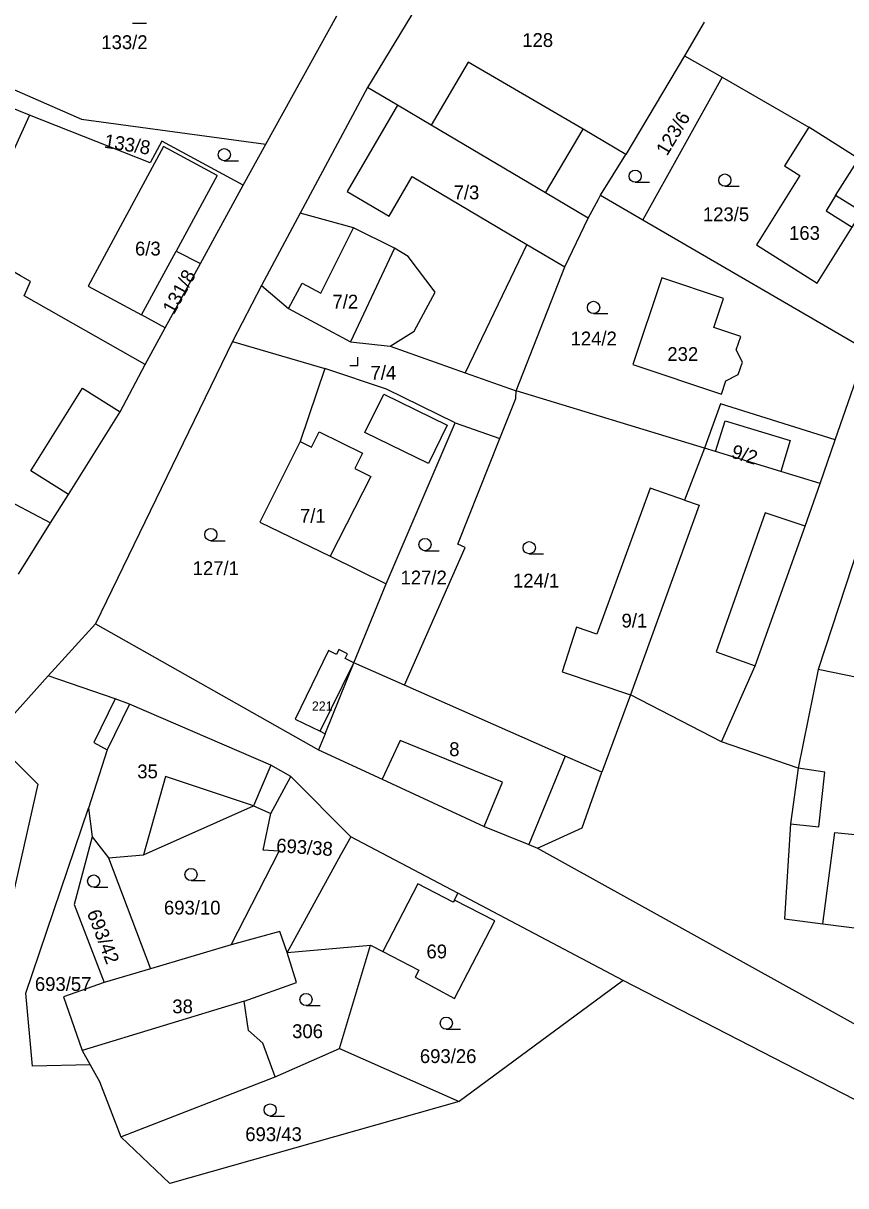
# Model space of a CAD drawing. Extents: x -7483133 to -743169, y -11317770 to -1127091.
# Drawn here: x -746438.1 to -746337, y -1132088.9 to -1131945.9 of the extents above; entities that cross this region are included whole.
import ezdxf

# ---------------------------------------------------------------- set-up
doc = ezdxf.new("R2010")
doc.units = 0
for name, color, linetype in [('Hranice parcel', 7, 'Continuous'), ('Parcelní čísla', 7, 'Continuous'), ('Vnitřní kresba', 7, 'Continuous'), ('Značky kultur', 7, 'Continuous')]:
    doc.layers.add(name, color=color, linetype=linetype)

msp = doc.modelspace()

# ---------------------------------------------------------------- linework, layer by layer
at = {"layer": 'Hranice parcel'}
for p, q in [((-746381.8, -1131930.69), (-746395.75, -1131953.81)), ((-746408.25, -1131960.77), (-746399.53, -1131945)), ((-746354.37, -1131945.76), (-746356.8, -1131949.89)), ((-746437.32, -1131957.2), (-746455.89, -1131949.78)), ((-746356.8, -1131949.89), (-746364, -1131962.05)), ((-746356.8, -1131949.89), (-746352.16, -1131952.55)), ((-746395.75, -1131953.81), (-746404.04, -1131969.28)), ((-746352.16, -1131952.55), (-746361.91, -1131970.09)), ((-746352.16, -1131952.55), (-746341.49, -1131958.67)), ((-746437.32, -1131957.2), (-746444.69, -1131973.38)), ((-746335.36, -1131962.56), (-746341.49, -1131958.67)), ((-746411.04, -1131965.81), (-746408.25, -1131960.77)), ((-746367.12, -1131967.06), (-746364, -1131962.05)), ((-746416.31, -1131975.44), (-746411.04, -1131965.81)), ((-746368.62, -1131969.86), (-746367.37, -1131967.53)), ((-746367.37, -1131967.53), (-746367.12, -1131967.06)), ((-746367.12, -1131967.06), (-746361.91, -1131970.09)), ((-746404.04, -1131969.28), (-746408.81, -1131978.18)), ((-746361.91, -1131970.09), (-746334.41, -1131986.06)), ((-746420.64, -1131983.36), (-746416.31, -1131975.44)), ((-746408.81, -1131978.18), (-746412.35, -1131985.06)), ((-746408.81, -1131978.18), (-746405.47, -1131981.01)), ((-746420.64, -1131983.36), (-746423.54, -1131981.79)), ((-746423.09, -1131987.89), (-746420.64, -1131983.36)), ((-746412.35, -1131985.06), (-746429.19, -1132019.77)), ((-746412.35, -1131985.06), (-746400.99, -1131988.36)), ((-746338.25, -1131997.16), (-746334.41, -1131986.06)), ((-746400.99, -1131988.36), (-746404.05, -1131997.34)), ((-746354.34, -1131998.17), (-746377.47, -1131991.14)), ((-746393.46, -1132014.85), (-746384.98, -1131995.05)), ((-746384.98, -1131995.05), (-746379.47, -1131997)), ((-746340.11, -1132002.51), (-746338.25, -1131997.16)), ((-746445.14, -1132001.9), (-746434.75, -1132007.36)), ((-746438.69, -1132013.68), (-746434.75, -1132007.36)), ((-746335.32, -1132010.03), (-746340.35, -1132025.42)), ((-746397.45, -1132024.58), (-746393.46, -1132014.85)), ((-746435.02, -1132026.19), (-746429.19, -1132019.77)), ((-746429.19, -1132019.77), (-746401.77, -1132035.28)), ((-746400.98, -1132033.31), (-746397.45, -1132024.58)), ((-746391.22, -1132027.33), (-746397.45, -1132024.58)), ((-746340.35, -1132025.42), (-746342.81, -1132037.56)), ((-746441.94, -1132033.89), (-746435.02, -1132026.19)), ((-746426.8, -1132029.03), (-746435.02, -1132026.19)), ((-746363.4, -1132028.51), (-746366.94, -1132038.04)), ((-746352.22, -1132034.3), (-746363.4, -1132028.51)), ((-746400.98, -1132033.31), (-746401.77, -1132035.28)), ((-746401.6, -1132033.01), (-746400.98, -1132033.31)), ((-746401.77, -1132035.28), (-746393.96, -1132038.89)), ((-746342.81, -1132037.56), (-746352.22, -1132034.3)), ((-746407.66, -1132043.13), (-746405.2, -1132038.56)), ((-746397.81, -1132045.97), (-746405.2, -1132038.56)), ((-746393.96, -1132038.89), (-746381.4, -1132044.7)), ((-746430.06, -1132042.48), (-746429.6, -1132046.01)), ((-746429.6, -1132046.01), (-746427.59, -1132048.57)), ((-746384.64, -1132052.93), (-746397.81, -1132045.97)), ((-746374.84, -1132047.38), (-746324.12, -1132075.54)), ((-746427.59, -1132048.57), (-746422.45, -1132062.24)), ((-746385.07, -1132053.77), (-746384.64, -1132052.93)), ((-746364.32, -1132063.67), (-746384.64, -1132052.93)), ((-746412.54, -1132059.26), (-746422.45, -1132062.24)), ((-746405.65, -1132060.22), (-746395.38, -1132059.32)), ((-746399.22, -1132072.05), (-746395.38, -1132059.32)), ((-746422.45, -1132062.24), (-746428.14, -1132063.91)), ((-746364.32, -1132063.67), (-746384.5, -1132078.54)), ((-746407.1, -1132075.5), (-746399.22, -1132072.05)), ((-746399.22, -1132072.05), (-746384.5, -1132078.54)), ((-746426.1, -1132082.89), (-746407.1, -1132075.5))]:
    msp.add_line(p, q, dxfattribs=at)
for points in [[(-746453.89, -1131947.67), (-746430.93, -1131957.68), (-746408.25, -1131960.77)], [(-746383.37, -1131950.7), (-746387.94, -1131958.43), (-746392.06, -1131955.99), (-746395.75, -1131953.81)], [(-746364, -1131962.05), (-746369.24, -1131958.95), (-746383.37, -1131950.7)], [(-746411.04, -1131965.81), (-746421.04, -1131960.39), (-746422.49, -1131963.07), (-746437.32, -1131957.2)], [(-746341.49, -1131958.67), (-746344.48, -1131963.46), (-746342.61, -1131964.63), (-746347.93, -1131973.15), (-746340.47, -1131977.86), (-746336.17, -1131971), (-746334.98, -1131969.11), (-746338.2, -1131967.09), (-746335.36, -1131962.56)], [(-746392.96, -1131985.62), (-746390.02, -1131983.77), (-746387.42, -1131978.99), (-746390.76, -1131974.61), (-746392.46, -1131973.55), (-746397.49, -1131971.05), (-746404.04, -1131969.28)], [(-746377.47, -1131991.14), (-746371.48, -1131975.87), (-746368.62, -1131969.86)], [(-746423.09, -1131987.89), (-746437.98, -1131979.44), (-746437.18, -1131977.66), (-746438.41, -1131976.96), (-746444.69, -1131973.38)], [(-746423.54, -1131981.79), (-746419.29, -1131973.93), (-746416.31, -1131975.44)], [(-746351.98, -1131979.75), (-746359.57, -1131977.21), (-746363.14, -1131987.9), (-746352.22, -1131991.54), (-746351.68, -1131989.88), (-746350.17, -1131989.11), (-746349.66, -1131987.58), (-746350.41, -1131986.06), (-746349.86, -1131984.42), (-746353.17, -1131983.31), (-746351.98, -1131979.75)], [(-746405.47, -1131981.01), (-746397.86, -1131985.09), (-746392.96, -1131985.62)], [(-746392.96, -1131985.62), (-746383.74, -1131988.91), (-746377.47, -1131991.14)], [(-746434.75, -1132007.36), (-746432.53, -1132003.87), (-746426.16, -1131993.7), (-746423.09, -1131987.89)], [(-746384.98, -1131995.05), (-746393.44, -1131990.91), (-746400.99, -1131988.36)], [(-746379.47, -1131997), (-746377.51, -1131992.07), (-746377.47, -1131991.14)], [(-746338.25, -1131997.16), (-746352.35, -1131992.71), (-746354.34, -1131998.17)], [(-746404.05, -1131997.34), (-746409, -1132007.27), (-746400.37, -1132011.48), (-746393.46, -1132014.85)], [(-746391.22, -1132027.33), (-746383.75, -1132010.4), (-746384.66, -1132010), (-746379.47, -1131997)], [(-746354.34, -1131998.17), (-746356.76, -1132004.57), (-746361.01, -1132003.1), (-746367.57, -1132021.06), (-746370.07, -1132020.2), (-746371.84, -1132025.7), (-746363.4, -1132028.51)], [(-746340.11, -1132002.51), (-746344.93, -1132001.03), (-746352.95, -1131998.59), (-746354.34, -1131998.17)], [(-746352.22, -1132034.3), (-746348.1, -1132024.97), (-746341.94, -1132007.79), (-746340.11, -1132002.51)], [(-746397.45, -1132024.58), (-746398.5, -1132024.07), (-746398.22, -1132023.48), (-746399.27, -1132022.95), (-746399.56, -1132023.55), (-746400.54, -1132023.07), (-746404.66, -1132031.52), (-746401.6, -1132033.01)], [(-746333.61, -1132057.47), (-746332.67, -1132049.65), (-746332.24, -1132046.07), (-746330.4, -1132030.76), (-746330, -1132027.47), (-746335.35, -1132026.41), (-746340.35, -1132025.42)], [(-746366.94, -1132038.04), (-746371.46, -1132036.05), (-746391.22, -1132027.33)], [(-746426.8, -1132029.03), (-746429.42, -1132034.4), (-746427.78, -1132035.27), (-746430.06, -1132042.48)], [(-746405.2, -1132038.56), (-746407.63, -1132037.16), (-746425.03, -1132029.66), (-746426.8, -1132029.03)], [(-746441.94, -1132033.89), (-746436.31, -1132039.52), (-746440.38, -1132057.72)], [(-746374.84, -1132047.38), (-746369.36, -1132044.89), (-746366.94, -1132038.04)], [(-746342.81, -1132037.56), (-746343.73, -1132044.39), (-746344.5, -1132056.09), (-746339.75, -1132056.69), (-746333.61, -1132057.47)], [(-746429.86, -1132074.04), (-746436.96, -1132074.19), (-746437.77, -1132065.23), (-746430.06, -1132042.48)], [(-746427.59, -1132048.57), (-746423.29, -1132048.22), (-746409.79, -1132042.16), (-746407.66, -1132043.13)], [(-746412.54, -1132059.26), (-746406.61, -1132047.75), (-746408.61, -1132047.62), (-746407.66, -1132043.13)], [(-746381.4, -1132044.7), (-746375.91, -1132046.94), (-746374.84, -1132047.38)], [(-746429.6, -1132046.01), (-746431.83, -1132054.3), (-746428.14, -1132063.91)], [(-746397.81, -1132045.97), (-746399.07, -1132048.25), (-746405.65, -1132060.22)], [(-746395.38, -1132059.32), (-746393.88, -1132060.1), (-746389.45, -1132062.38), (-746389.91, -1132063.27), (-746385.05, -1132065.88), (-746380.12, -1132056.33), (-746385.07, -1132053.77)], [(-746405.65, -1132060.22), (-746406.55, -1132057.63), (-746412.54, -1132059.26)], [(-746407.1, -1132075.5), (-746408.64, -1132071.36), (-746410.41, -1132069.82), (-746410.94, -1132066.21), (-746404.49, -1132063.91), (-746405.65, -1132060.22)], [(-746428.14, -1132063.91), (-746433.13, -1132065.67), (-746430.83, -1132072.28), (-746429.86, -1132074.04)], [(-746281.98, -1132106.18), (-746317.29, -1132087.85), (-746364.32, -1132063.67)], [(-746429.86, -1132074.04), (-746428.72, -1132076.1), (-746426.1, -1132082.89)], [(-746384.5, -1132078.54), (-746420.08, -1132088.64), (-746426.1, -1132082.89)]]:
    msp.add_lwpolyline(points, dxfattribs=at)
at = {"layer": 'Vnitřní kresba'}
for p, q in [((-746392.06, -1131955.99), (-746398.27, -1131966.61)), ((-746373.86, -1131966.76), (-746387.94, -1131958.43)), ((-746373.86, -1131966.76), (-746369.24, -1131958.95)), ((-746420.84, -1131961.07), (-746430.12, -1131978.23)), ((-746414.26, -1131964.63), (-746420.84, -1131961.07)), ((-746414.26, -1131964.63), (-746419.29, -1131973.93)), ((-746393.11, -1131969.63), (-746390.26, -1131964.74)), ((-746390.26, -1131964.74), (-746376.15, -1131973.1)), ((-746398.27, -1131966.61), (-746393.11, -1131969.63)), ((-746368.62, -1131969.86), (-746373.86, -1131966.76)), ((-746338.2, -1131967.09), (-746339.38, -1131968.98)), ((-746339.38, -1131968.98), (-746336.17, -1131971)), ((-746401.49, -1131979.09), (-746397.49, -1131971.05)), ((-746392.46, -1131973.55), (-746397.86, -1131985.09)), ((-746376.15, -1131973.1), (-746383.74, -1131988.91)), ((-746376.15, -1131973.1), (-746371.48, -1131975.87)), ((-746430.12, -1131978.23), (-746423.54, -1131981.79)), ((-746405.47, -1131981.01), (-746403.78, -1131977.86)), ((-746403.78, -1131977.86), (-746401.49, -1131979.09)), ((-746437.16, -1132000.97), (-746430.81, -1131990.79)), ((-746430.81, -1131990.79), (-746426.16, -1131993.7)), ((-746396.07, -1131996.26), (-746393.75, -1131991.54)), ((-746393.75, -1131991.54), (-746385.96, -1131995.34)), ((-746385.96, -1131995.34), (-746388.24, -1132000.05)), ((-746352.95, -1131998.59), (-746351.8, -1131994.81)), ((-746351.8, -1131994.81), (-746343.78, -1131997.25)), ((-746402.65, -1131998.04), (-746401.71, -1131996.16)), ((-746401.71, -1131996.16), (-746396.39, -1131998.81)), ((-746388.24, -1132000.05), (-746396.07, -1131996.26)), ((-746404.05, -1131997.34), (-746402.65, -1131998.04)), ((-746343.78, -1131997.25), (-746344.93, -1132001.03)), ((-746396.39, -1131998.81), (-746397.32, -1132000.69)), ((-746432.53, -1132003.87), (-746437.16, -1132000.97)), ((-746397.32, -1132000.69), (-746395.34, -1132001.68)), ((-746395.34, -1132001.68), (-746400.37, -1132011.48)), ((-746354.99, -1132005.18), (-746363.4, -1132028.51)), ((-746356.76, -1132004.57), (-746354.99, -1132005.18)), ((-746346.85, -1132006.12), (-746352.9, -1132023.25)), ((-746341.94, -1132007.79), (-746346.85, -1132006.12)), ((-746352.9, -1132023.25), (-746348.1, -1132024.97)), ((-746401.6, -1132033.01), (-746397.45, -1132024.58)), ((-746425.03, -1132029.66), (-746427.78, -1132035.27)), ((-746391.76, -1132034.12), (-746393.96, -1132038.89)), ((-746379.18, -1132039.26), (-746391.76, -1132034.12)), ((-746371.46, -1132036.05), (-746375.91, -1132046.94)), ((-746407.63, -1132037.16), (-746409.79, -1132042.16)), ((-746339.51, -1132038.02), (-746342.81, -1132037.56)), ((-746340.28, -1132044.78), (-746339.51, -1132038.02)), ((-746420.61, -1132038.55), (-746423.29, -1132048.22)), ((-746409.79, -1132042.16), (-746420.61, -1132038.55)), ((-746381.4, -1132044.7), (-746379.18, -1132039.26)), ((-746343.73, -1132044.39), (-746340.28, -1132044.78)), ((-746339.75, -1132056.69), (-746338.28, -1132045.47)), ((-746338.28, -1132045.47), (-746332.24, -1132046.07)), ((-746389.59, -1132051.78), (-746393.88, -1132060.1)), ((-746385.21, -1132054.04), (-746389.59, -1132051.78)), ((-746385.07, -1132053.77), (-746385.21, -1132054.04)), ((-746410.94, -1132066.21), (-746430.83, -1132072.28))]:
    msp.add_line(p, q, dxfattribs=at)
at = {"layer": 'Značky kultur'}
for p, q in [((-746424.67, -1131945.9), (-746422.92, -1131945.9)), ((-746413.37, -1131962.82), (-746411.62, -1131962.82)), ((-746362.84, -1131965.46), (-746361.09, -1131965.46)), ((-746351.82, -1131965.94), (-746350.07, -1131965.94)), ((-746367.96, -1131981.61), (-746366.21, -1131981.61)), ((-746397.94, -1131988), (-746396.94, -1131988)), ((-746396.94, -1131988), (-746396.94, -1131987)), ((-746415.03, -1132009.56), (-746413.28, -1132009.56)), ((-746388.69, -1132010.79), (-746386.94, -1132010.79)), ((-746375.87, -1132011.17), (-746374.12, -1132011.17)), ((-746429.43, -1132052.18), (-746427.68, -1132052.18)), ((-746417.46, -1132051.37), (-746415.71, -1132051.37)), ((-746403.32, -1132066.75), (-746401.57, -1132066.75)), ((-746386.07, -1132069.67), (-746384.32, -1132069.67)), ((-746407.73, -1132080.34), (-746405.98, -1132080.34))]:
    msp.add_line(p, q, dxfattribs=at)
for centre in [(-746413.37, -1131962.07), (-746362.84, -1131964.71), (-746351.82, -1131965.19), (-746367.96, -1131980.86), (-746415.03, -1132008.81), (-746388.69, -1132010.04), (-746375.87, -1132010.42), (-746429.43, -1132051.43), (-746417.46, -1132050.62), (-746403.32, -1132066), (-746386.07, -1132068.92), (-746407.73, -1132079.59)]:
    msp.add_circle(centre, 0.75, dxfattribs=at)

# ---------------------------------------------------------------- texts
at = {"layer": 'Parcelní čísla'}
for s, height, p in [('133/2', 1.7, (-746428.49, -1131949.08)), ('128', 1.7, (-746376.73, -1131948.82)), ('7/3', 1.7, (-746385.17, -1131967.56)), ('123/5', 1.7, (-746354.52, -1131970.25)), ('163', 1.7, (-746343.92, -1131972.55)), ('6/3', 1.7, (-746424.35, -1131974.47)), ('7/2', 1.7, (-746400.07, -1131981)), ('124/2', 1.7, (-746370.79, -1131985.53)), ('232', 1.7, (-746358.89, -1131987.45)), ('7/4', 1.7, (-746395.39, -1131989.75)), ('7/1', 1.7, (-746404.06, -1132007.34)), ('127/1', 1.7, (-746417.26, -1132013.79)), ('127/2', 1.7, (-746391.7, -1132014.94)), ('124/1', 1.7, (-746377.87, -1132015.32)), ('9/1', 1.7, (-746364.52, -1132020.24)), ('221', 1.14, (-746402.6, -1132030.48)), ('8', 1.7, (-746385.71, -1132036.06)), ('35', 1.7, (-746424.07, -1132038.79)), ('693/10', 1.7, (-746420.79, -1132055.55)), ('69', 1.7, (-746388.51, -1132060.94)), ('693/57', 1.7, (-746436.66, -1132064.95)), ('38', 1.7, (-746419.76, -1132067.7)), ('306', 1.7, (-746405.03, -1132070.75)), ('693/26', 1.7, (-746389.32, -1132073.82)), ('693/43', 1.7, (-746410.79, -1132083.42))]:
    msp.add_text(s, height=height, dxfattribs=at).set_placement(p)
for s, rotation, p in [('123/6', 59, (-746358.93, -1131962.31)), ('133/8', 351, (-746428.23, -1131961.19)), ('131/8', 61, (-746419.57, -1131981.81)), ('9/2', 343, (-746351.14, -1131999.31)), ('693/38', 356, (-746407.03, -1132047.87)), ('693/42', 291, (-746430.3, -1132055.32))]:
    msp.add_text(s, height=1.7, rotation=rotation, dxfattribs=at).set_placement(p)

doc.saveas('drawing.dxf')
